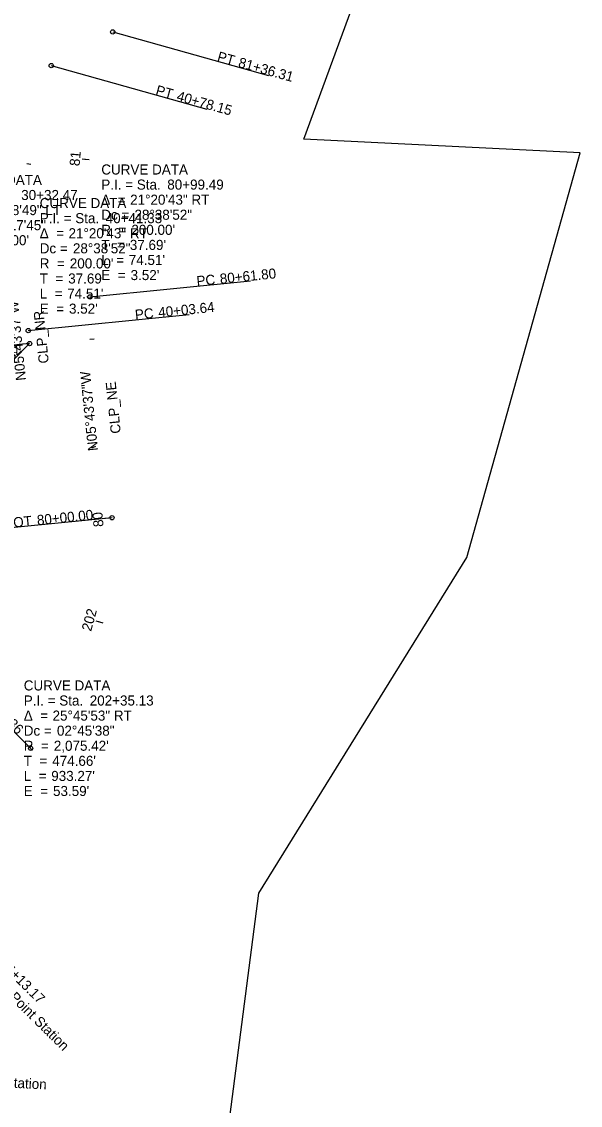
# Model space of a CAD drawing. Extents: x 1564517 to 1565226, y 635740 to 637455.
# Drawn here: x 1564889.4 to 1565045, y 636329.5 to 636631.2 of the extents above; entities that cross this region are included whole.
import ezdxf

# ---------------------------------------------------------------- set-up
doc = ezdxf.new("R2010")
doc.units = 0
for name, color, linetype in [('GK_Drainage_Nodes', 7, 'Continuous'), ('SC_Scratch10', 7, 'Continuous'), ('TX_P_1000', 7, 'Continuous'), ('UT_P_Water', 7, 'Continuous'), ('UT_P_Water_Cells', 7, 'Continuous'), ('UT_X_Electric', 7, 'Continuous'), ('UT_X_Sanitary_Pressure_Line', 7, 'Continuous'), ('UT_X_Water_Cells', 7, 'Continuous')]:
    doc.layers.add(name, color=color, linetype=linetype)

msp = doc.modelspace()

# ---------------------------------------------------------------- linework, layer by layer
at = {"layer": 'TX_P_1000'}
for p, q in [((1564897.65, 636619.02), (1564940.99, 636606.9)), ((1564891.27, 636545.22), (1564936.04, 636549.71)), ((1564891.63, 636541.59), (1564846.86, 636537.1)), ((1564891.63, 636541.59), (1564859.77, 636509.82))]:
    msp.add_line(p, q, dxfattribs=at)
at = {"layer": 'UT_P_Water_Cells'}
for p, q in [((1564914.81, 636628.37), (1564958.15, 636616.26)), ((1564897.65, 636619.02), (1564940.99, 636606.9)), ((1564908.25, 636592.72), (1564907.06, 636592.83)), ((1564908.42, 636554.57), (1564953.2, 636559.06)), ((1564891.27, 636545.22), (1564936.04, 636549.71)), ((1564891.63, 636541.59), (1564846.86, 636537.1)), ((1564891.63, 636541.59), (1564859.77, 636509.82)), ((1564891.63, 636541.59), (1564889.64, 636541.39)), ((1564914.59, 636493.08), (1564869.81, 636488.59)), ((1564914.59, 636493.08), (1564912.6, 636492.88)), ((1564912.09, 636463.76), (1564910.93, 636464.08)), ((1564891.93, 636428.91), (1564859.9, 636460.52))]:
    msp.add_line(p, q, dxfattribs=at)
for centre in [(1564914.81, 636628.37), (1564897.65, 636619.02), (1564908.42, 636554.57), (1564891.27, 636545.22), (1564891.63, 636541.59), (1564891.63, 636541.59), (1564914.59, 636493.08), (1564891.93, 636428.91)]:
    msp.add_circle(centre, 0.6, dxfattribs=at)
at = {"layer": 'UT_X_Electric'}
msp.add_lwpolyline([(1564685.49, 636222.38), (1564930.72, 636197.15), (1564955.53, 636388.56), (1565013.42, 636482), (1565045.03, 636594.7), (1564968.04, 636598.47), (1565001.39, 636689.39), (1564864.83, 636740.08), (1564842.01, 636748.56), (1564682.06, 636752.05), (1564649.71, 636425.72), (1564708.41, 636418.15)], close=True, dxfattribs=at)
at = {"layer": 'UT_X_Sanitary_Pressure_Line'}
for p, q in [((1564914.81, 636628.37), (1564958.15, 636616.26)), ((1564897.65, 636619.02), (1564940.99, 636606.9)), ((1564908.42, 636554.57), (1564953.2, 636559.06)), ((1564891.27, 636545.22), (1564936.04, 636549.71)), ((1564891.63, 636541.59), (1564846.86, 636537.1)), ((1564891.63, 636541.59), (1564859.77, 636509.82)), ((1564891.63, 636541.59), (1564889.64, 636541.39)), ((1564914.59, 636493.08), (1564869.81, 636488.59)), ((1564914.59, 636493.08), (1564912.6, 636492.88)), ((1564891.93, 636428.91), (1564859.9, 636460.52))]:
    msp.add_line(p, q, dxfattribs=at)
for centre in [(1564914.81, 636628.37), (1564897.65, 636619.02), (1564908.42, 636554.57), (1564891.27, 636545.22), (1564891.63, 636541.59), (1564891.63, 636541.59), (1564914.59, 636493.08), (1564891.93, 636428.91)]:
    msp.add_circle(centre, 0.6, dxfattribs=at)
at = {"layer": 'UT_X_Water_Cells'}
for p, q in [((1564892.01, 636591.46), (1564890.82, 636591.62)), ((1564908.25, 636592.72), (1564906.26, 636592.9)), ((1564909.6, 636542.83), (1564908.4, 636542.71)), ((1564891.63, 636541.59), (1564889.64, 636541.39)), ((1564910, 636512.91), (1564908.87, 636512.49)), ((1564914.59, 636493.08), (1564912.6, 636492.88)), ((1564912.09, 636463.76), (1564910.16, 636464.29))]:
    msp.add_line(p, q, dxfattribs=at)
for centre in [(1564897.65, 636619.02), (1564891.27, 636545.22), (1564891.63, 636541.59), (1564891.63, 636541.59)]:
    msp.add_circle(centre, 0.6, dxfattribs=at)

# ---------------------------------------------------------------- texts
at = {"layer": 'GK_Drainage_Nodes'}
for s, p in [('CURVE DATA', (1564911.61, 636588.67)), ('CURVE DATA', (1564870.93, 636585.77)), ('30+32.47', (1564889.3, 636581.57)), ('P.I. = Sta. ', (1564911.61, 636584.47)), ('80+99.49', (1564929.98, 636584.47)), ('CURVE DATA', (1564894.46, 636579.32)), ('Δ  = ', (1564911.61, 636580.27)), ('21°20\'43" RT', (1564919.64, 636580.27)), ('35°58\'49" LT', (1564878.95, 636577.37)), ('Dc = ', (1564911.61, 636576.07)), ('28°38\'52"', (1564920.85, 636576.07)), ('57°17\'45"', (1564880.17, 636573.17)), ('P.I. = Sta. ', (1564894.46, 636575.12)), ('40+41.33', (1564912.83, 636575.12)), ('Δ  = ', (1564894.46, 636570.92)), ('21°20\'43" RT', (1564902.48, 636570.92)), ('R  = ', (1564911.61, 636571.87)), ("200.00'", (1564919.98, 636571.87)), ("100.00'", (1564879.3, 636568.97)), ('Dc = ', (1564894.46, 636566.72)), ('28°38\'52"', (1564903.7, 636566.72)), ('T  = ', (1564911.61, 636567.67)), ("37.69'", (1564919.55, 636567.67)), ('L  = ', (1564911.61, 636563.47)), ("74.51'", (1564919.26, 636563.47)), ('R  = ', (1564894.46, 636562.52)), ("200.00'", (1564902.83, 636562.52)), ('T  = ', (1564894.46, 636558.32)), ("37.69'", (1564902.39, 636558.32)), ('E  = ', (1564911.61, 636559.27)), ("3.52'", (1564919.77, 636559.27)), ('L  = ', (1564894.46, 636554.12)), ("74.51'", (1564902.11, 636554.12)), ('E  = ', (1564894.46, 636549.92)), ("3.52'", (1564902.61, 636549.92)), ('CURVE DATA', (1564890.01, 636444.99)), ('P.I. = Sta. ', (1564890.01, 636440.79)), ('202+35.13', (1564908.38, 636440.79)), ('Δ  = ', (1564890.01, 636436.59)), ('25°45\'53" RT', (1564898.03, 636436.59)), ('Dc = ', (1564890.01, 636432.39)), ('02°45\'38"', (1564899.25, 636432.39)), ('R  = ', (1564890.01, 636428.19)), ("2,075.42'", (1564898.38, 636428.19)), ('T  = ', (1564890.01, 636423.99)), ("474.66'", (1564897.94, 636423.99)), ('L  = ', (1564890.01, 636419.79)), ("933.27'", (1564897.66, 636419.79)), ('E  = ', (1564890.01, 636415.59)), ("53.59'", (1564898.16, 636415.59))]:
    msp.add_text(s, height=2.8, dxfattribs=at).set_placement(p)
for s, p in [('N05°43\'37"W', (1564890.64, 636531.4)), ('CLP_NR', (1564897, 636536.19)), ('N05°43\'37"W', (1564910.7, 636511.82)), ('CLP_NE', (1564917.05, 636516.65))]:
    msp.add_text(s, height=2.8, rotation=95.727, dxfattribs=at).set_placement(p)
at = {"layer": 'SC_Scratch10'}
for s, p in [('CURVE DATA', (1564911.61, 636588.67)), ('CURVE DATA', (1564870.93, 636585.77)), ('30+32.47', (1564889.3, 636581.57)), ('P.I. = Sta. ', (1564911.61, 636584.47)), ('80+99.49', (1564929.98, 636584.47)), ('CURVE DATA', (1564894.46, 636579.32)), ('Δ  = ', (1564911.61, 636580.27)), ('21°20\'43" RT', (1564919.64, 636580.27)), ('35°58\'49" LT', (1564878.95, 636577.37)), ('Dc = ', (1564911.61, 636576.07)), ('28°38\'52"', (1564920.85, 636576.07)), ('57°17\'45"', (1564880.17, 636573.17)), ('P.I. = Sta. ', (1564894.46, 636575.12)), ('40+41.33', (1564912.83, 636575.12)), ('Δ  = ', (1564894.46, 636570.92)), ('21°20\'43" RT', (1564902.48, 636570.92)), ('R  = ', (1564911.61, 636571.87)), ("200.00'", (1564919.98, 636571.87)), ("100.00'", (1564879.3, 636568.97)), ('Dc = ', (1564894.46, 636566.72)), ('28°38\'52"', (1564903.7, 636566.72)), ('T  = ', (1564911.61, 636567.67)), ("37.69'", (1564919.55, 636567.67)), ('L  = ', (1564911.61, 636563.47)), ("74.51'", (1564919.26, 636563.47)), ('R  = ', (1564894.46, 636562.52)), ("200.00'", (1564902.83, 636562.52)), ('T  = ', (1564894.46, 636558.32)), ("37.69'", (1564902.39, 636558.32)), ('E  = ', (1564911.61, 636559.27)), ("3.52'", (1564919.77, 636559.27)), ('L  = ', (1564894.46, 636554.12)), ("74.51'", (1564902.11, 636554.12)), ('E  = ', (1564894.46, 636549.92)), ("3.52'", (1564902.61, 636549.92)), ('CURVE DATA', (1564890.01, 636444.99)), ('P.I. = Sta. ', (1564890.01, 636440.79)), ('202+35.13', (1564908.38, 636440.79)), ('Δ  = ', (1564890.01, 636436.59)), ('25°45\'53" RT', (1564898.03, 636436.59)), ('Dc = ', (1564890.01, 636432.39)), ('02°45\'38"', (1564899.25, 636432.39)), ('R  = ', (1564890.01, 636428.19)), ("2,075.42'", (1564898.38, 636428.19)), ('T  = ', (1564890.01, 636423.99)), ("474.66'", (1564897.94, 636423.99)), ('L  = ', (1564890.01, 636419.79)), ("933.27'", (1564897.66, 636419.79)), ('E  = ', (1564890.01, 636415.59)), ("53.59'", (1564898.16, 636415.59))]:
    msp.add_text(s, height=2.8, dxfattribs=at).set_placement(p)
for s, p in [('N05°43\'37"W', (1564890.64, 636531.4)), ('CLP_NR', (1564897, 636536.19)), ('N05°43\'37"W', (1564910.7, 636511.82)), ('CLP_NE', (1564917.05, 636516.65))]:
    msp.add_text(s, height=2.8, rotation=95.727, dxfattribs=at).set_placement(p)
at = {"layer": 'TX_P_1000'}
for rotation, p in [(315.3822, (1564864.23, 636380.66)), (356.99, (1564844.77, 636336.58))]:
    msp.add_text('Linear Annotation.Point Station', height=2.8, rotation=rotation, dxfattribs=at).set_placement(p)
at = {"layer": 'UT_P_Water'}
for s, p in [('CURVE DATA', (1564911.61, 636588.67)), ('CURVE DATA', (1564870.93, 636585.77)), ('30+32.47', (1564889.3, 636581.57)), ('P.I. = Sta. ', (1564911.61, 636584.47)), ('80+99.49', (1564929.98, 636584.47)), ('CURVE DATA', (1564894.46, 636579.32)), ('Δ  = ', (1564911.61, 636580.27)), ('21°20\'43" RT', (1564919.64, 636580.27)), ('35°58\'49" LT', (1564878.95, 636577.37)), ('Dc = ', (1564911.61, 636576.07)), ('28°38\'52"', (1564920.85, 636576.07)), ('57°17\'45"', (1564880.17, 636573.17)), ('P.I. = Sta. ', (1564894.46, 636575.12)), ('40+41.33', (1564912.83, 636575.12)), ('Δ  = ', (1564894.46, 636570.92)), ('21°20\'43" RT', (1564902.48, 636570.92)), ('R  = ', (1564911.61, 636571.87)), ("200.00'", (1564919.98, 636571.87)), ("100.00'", (1564879.3, 636568.97)), ('Dc = ', (1564894.46, 636566.72)), ('28°38\'52"', (1564903.7, 636566.72)), ('T  = ', (1564911.61, 636567.67)), ("37.69'", (1564919.55, 636567.67)), ('L  = ', (1564911.61, 636563.47)), ("74.51'", (1564919.26, 636563.47)), ('R  = ', (1564894.46, 636562.52)), ("200.00'", (1564902.83, 636562.52)), ('T  = ', (1564894.46, 636558.32)), ("37.69'", (1564902.39, 636558.32)), ('E  = ', (1564911.61, 636559.27)), ("3.52'", (1564919.77, 636559.27)), ('L  = ', (1564894.46, 636554.12)), ("74.51'", (1564902.11, 636554.12)), ('E  = ', (1564894.46, 636549.92)), ("3.52'", (1564902.61, 636549.92)), ('CURVE DATA', (1564890.01, 636444.99)), ('P.I. = Sta. ', (1564890.01, 636440.79)), ('202+35.13', (1564908.38, 636440.79)), ('Δ  = ', (1564890.01, 636436.59)), ('25°45\'53" RT', (1564898.03, 636436.59)), ('Dc = ', (1564890.01, 636432.39)), ('02°45\'38"', (1564899.25, 636432.39)), ('R  = ', (1564890.01, 636428.19)), ("2,075.42'", (1564898.38, 636428.19)), ('T  = ', (1564890.01, 636423.99)), ("474.66'", (1564897.94, 636423.99)), ('L  = ', (1564890.01, 636419.79)), ("933.27'", (1564897.66, 636419.79)), ('E  = ', (1564890.01, 636415.59)), ("53.59'", (1564898.16, 636415.59))]:
    msp.add_text(s, height=2.8, dxfattribs=at).set_placement(p)
for s, p in [('N05°43\'37"W', (1564890.64, 636531.4)), ('CLP_NR', (1564897, 636536.19)), ('N05°43\'37"W', (1564910.7, 636511.82)), ('CLP_NE', (1564917.05, 636516.65))]:
    msp.add_text(s, height=2.8, rotation=95.727, dxfattribs=at).set_placement(p)
at = {"layer": 'UT_P_Water_Cells'}
for s, rotation, p in [('PT', 344.3818, (1564943.7, 636620.3)), ('81+36.31', 344.3818, (1564949.56, 636618.66)), ('PT', 344.3818, (1564926.55, 636610.94)), ('40+78.15', 344.3818, (1564932.41, 636609.3)), ('PC', 5.727, (1564938.27, 636557.57)), ('80+61.80', 5.727, (1564944.76, 636558.22)), ('PC', 5.727, (1564921.12, 636548.21)), ('40+03.64', 5.727, (1564927.61, 636548.86)), ('202+84.32', 44.922, (1564877.01, 636527.01)), ('80+00.00', 5.727, (1564893.82, 636491)), ('80', 95.727, (1564912.27, 636490.65)), ('POT', 5.727, (1564884.74, 636490.09)), ('74+62.36', 315.3822, (1564877.08, 636443.57)), ('74+13.17', 315.3822, (1564883.07, 636368.55))]:
    msp.add_text(s, height=2.8, rotation=rotation, dxfattribs=at).set_placement(p)
at = {"layer": 'UT_X_Sanitary_Pressure_Line'}
for s, rotation, p in [('PT', 344.3818, (1564943.7, 636620.3)), ('81+36.31', 344.3818, (1564949.56, 636618.66)), ('PT', 344.3818, (1564926.55, 636610.94)), ('40+78.15', 344.3818, (1564932.41, 636609.3)), ('PC', 5.727, (1564938.27, 636557.57)), ('80+61.80', 5.727, (1564944.76, 636558.22)), ('PC', 5.727, (1564921.12, 636548.21)), ('40+03.64', 5.727, (1564927.61, 636548.86)), ('202+84.32', 44.922, (1564877.01, 636527.01)), ('80+00.00', 5.727, (1564893.82, 636491)), ('80', 95.727, (1564912.27, 636490.65)), ('POT', 5.727, (1564884.74, 636490.09)), ('74+62.36', 315.3822, (1564877.08, 636443.57)), ('74+13.17', 315.3822, (1564883.07, 636368.55))]:
    msp.add_text(s, height=2.8, rotation=rotation, dxfattribs=at).set_placement(p)
at = {"layer": 'UT_X_Water_Cells'}
for s, rotation, p in [('81', 84.7826, (1564905.53, 636590.93)), ('80', 95.727, (1564912.27, 636490.65)), ('202', 74.5294, (1564908.76, 636461.29))]:
    msp.add_text(s, height=2.8, rotation=rotation, dxfattribs=at).set_placement(p)

doc.saveas('drawing.dxf')
